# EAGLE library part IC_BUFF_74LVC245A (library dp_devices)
Octal Bus transceiver with 3-state, 3.3V supply
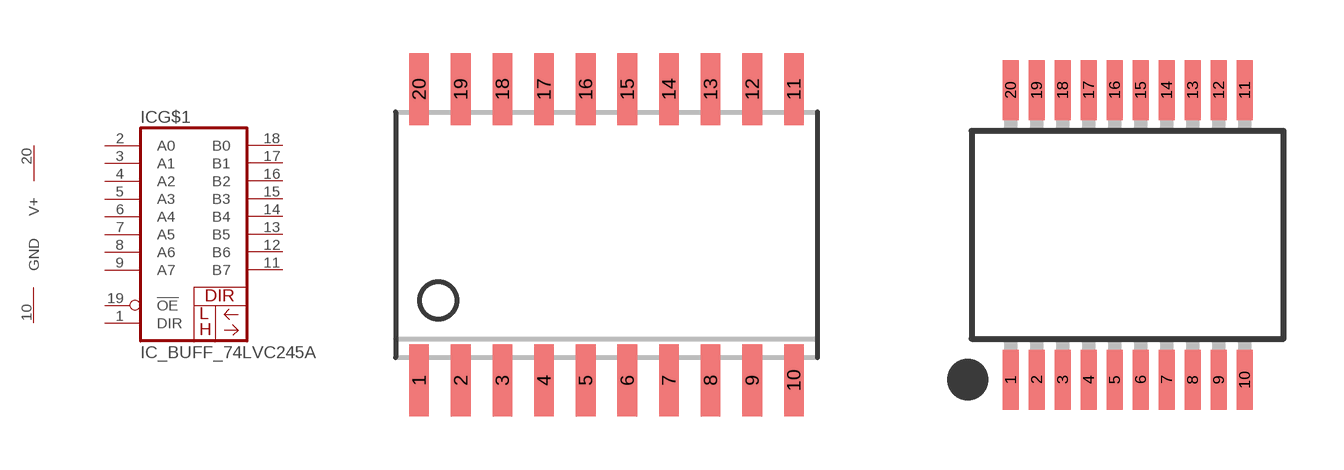
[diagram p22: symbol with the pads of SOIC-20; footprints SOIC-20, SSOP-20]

Designator prefix IC; gates G$1=74LVC245A SUPPLY=SUPPLY

## IC_BUFF_74LVC245A-SOIC20  [SOIC-20]
1  G$1:DIR  in
2  G$1:A0
3  G$1:A1
4  G$1:A2
5  G$1:A3
6  G$1:A4
7  G$1:A5
8  G$1:A6
9  G$1:A7
10  SUPPLY:GND  sup
11  G$1:B7
12  G$1:B6
13  G$1:B5
14  G$1:B4
15  G$1:B3
16  G$1:B2
17  G$1:B1
18  G$1:B0
19  G$1:!OE  in
20  SUPPLY:V+  sup

## IC_BUFF_74LVC245A-SSOP20  [SSOP-20]
Pads as for SOIC-20

## Footprint SOIC-20 (pad centres in mm)
smd 0.6 x 2.2: 1 -5.715,-4.445; 2 -4.445,-4.445; 3 -3.175,-4.445; 4 -1.905,-4.445; 5 -0.635,-4.445; 6 0.635,-4.445; 7 1.905,-4.445; 8 3.175,-4.445; 9 4.445,-4.445; 10 5.715,-4.445; 11 5.715,4.445; 12 4.445,4.445; 13 3.175,4.445; 14 1.905,4.445; 15 0.635,4.445; 16 -0.635,4.445; 17 -1.905,4.445; 18 -3.175,4.445; 19 -4.445,4.445; 20 -5.715,4.445

## Footprint SSOP-20 (pad centres in mm)
smd 0.4 x 1.5: 1 -2.925,-3.625; 2 -2.275,-3.625; 3 -1.625,-3.625; 4 -0.975,-3.625; 5 -0.325,-3.625; 6 0.325,-3.625; 7 0.975,-3.625; 8 1.625,-3.625; 9 2.275,-3.625; 10 2.925,-3.625; 11 2.925,3.625; 12 2.275,3.625; 13 1.625,3.625; 14 0.975,3.625; 15 0.325,3.625; 16 -0.325,3.625; 17 -0.975,3.625; 18 -1.625,3.625; 19 -2.275,3.625; 20 -2.925,3.625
